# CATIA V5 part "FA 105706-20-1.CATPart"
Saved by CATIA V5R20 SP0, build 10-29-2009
Part number: FA 105706-20-1
Revision: ANY
Definition: UNKNOWN
Nomenclature: FA 105706-20-1
Source: Unknown
Bounding box of the stored display mesh (mm): x -5 to 5, y -10 to 10, z -5 to 5
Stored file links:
  C:\Users\Utente\Desktop\IO LAVORO\3D X SITO CF\CUMSA\3D files FA\FA 105706-20\FA 105706-20-1.CATPart

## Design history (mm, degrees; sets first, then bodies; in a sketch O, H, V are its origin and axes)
Body1 "Cortar-Extruir5" (main body)
  Solid1: solid without history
